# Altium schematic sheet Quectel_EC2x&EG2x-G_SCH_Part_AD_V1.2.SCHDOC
size A4
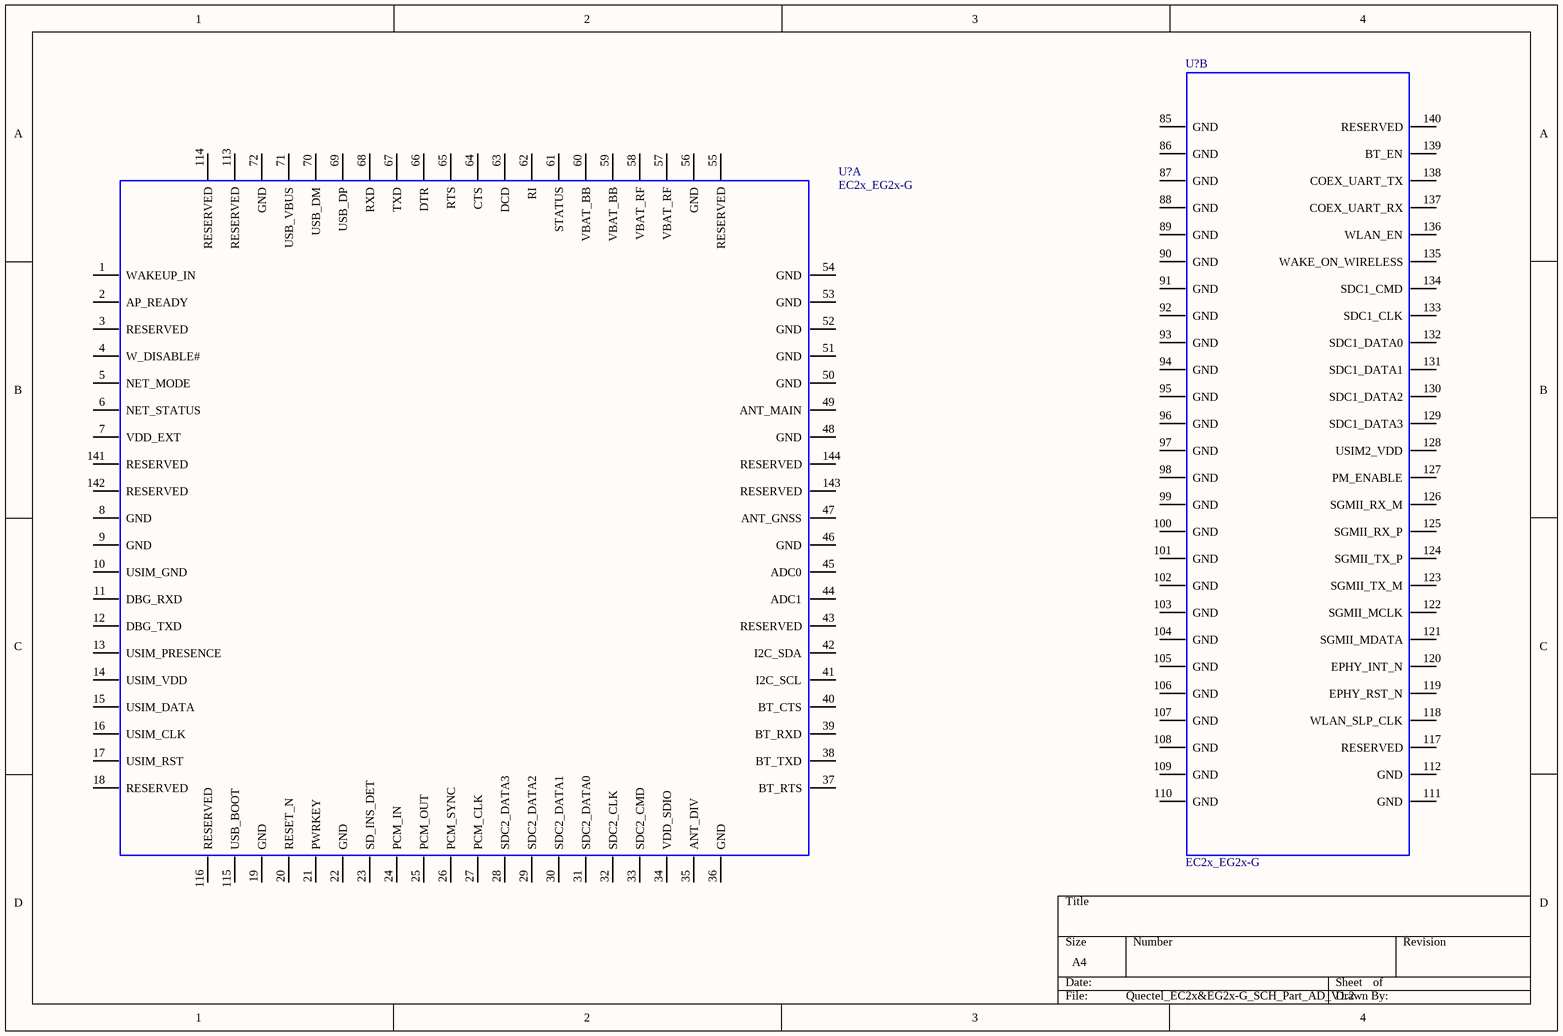
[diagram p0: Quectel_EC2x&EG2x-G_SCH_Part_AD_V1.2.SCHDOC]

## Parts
(Parts that share a designator on the sheet are numbered #1, #2 ... from top to bottom, then left to right.)
U?#1  EC2x_EG2x-G  (part B of 2)
U?#2  EC2x_EG2x-G  (part A of 2)

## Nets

Not connected (* = marked no-connect by the designer): U?#1 85(GND) 86(GND) 87(GND) 88(GND) 89(GND) 90(GND) 91(GND) 92(GND) 93(GND) 94(GND) 95(GND) 96(GND) 97(GND) 98(GND) 99(GND) 100(GND) 101(GND) 102(GND) 103(GND) 104(GND) 105(GND) 106(GND) 107(GND) 108(GND) 109(GND) 110(GND) 111(GND) 112(GND) 117(RESERVED) 118(WLAN_SLP_CLK) 119(EPHY_RST_N) 120(EPHY_INT_N) 121(SGMII_MDATA) 122(SGMII_MCLK) 123(SGMII_TX_M) 124(SGMII_TX_P) 125(SGMII_RX_P) 126(SGMII_RX_M) 127(PM_ENABLE) 128(USIM2_VDD) 129(SDC1_DATA3) 130(SDC1_DATA2) 131(SDC1_DATA1) 132(SDC1_DATA0) 133(SDC1_CLK) 134(SDC1_CMD) 135(WAKE_ON_WIRELESS) 136(WLAN_EN) 137(COEX_UART_RX) 138(COEX_UART_TX) 139(BT_EN) 140(RESERVED); U?#2 1(WAKEUP_IN) 2(AP_READY) 3(RESERVED) 4(W_DISABLE#) 5(NET_MODE) 6(NET_STATUS) 7(VDD_EXT) 8(GND) 9(GND) 10(USIM_GND) 11(DBG_RXD) 12(DBG_TXD) 13(USIM_PRESENCE) 14(USIM_VDD) 15(USIM_DATA) 16(USIM_CLK) 17(USIM_RST) 18(RESERVED) 19(GND) 20(RESET_N) 21(PWRKEY) 22(GND) 23(SD_INS_DET) 24(PCM_IN) 25(PCM_OUT) 26(PCM_SYNC) 27(PCM_CLK) 28(SDC2_DATA3) 29(SDC2_DATA2) 30(SDC2_DATA1) 31(SDC2_DATA0) 32(SDC2_CLK) 33(SDC2_CMD) 34(VDD_SDIO) 35(ANT_DIV) 36(GND) 37(BT_RTS) 38(BT_TXD) 39(BT_RXD) 40(BT_CTS) 41(I2C_SCL) 42(I2C_SDA) 43(RESERVED) 44(ADC1) 45(ADC0) 46(GND) 47(ANT_GNSS) 48(GND) 49(ANT_MAIN) 50(GND) 51(GND) 52(GND) 53(GND) 54(GND) 55(RESERVED) 56(GND) 57(VBAT_RF) 58(VBAT_RF) 59(VBAT_BB) 60(VBAT_BB) 61(STATUS) 62(RI) 63(DCD) 64(CTS) 65(RTS) 66(DTR) 67(TXD) 68(RXD) 69(USB_DP) 70(USB_DM) 71(USB_VBUS) 72(GND) 113(RESERVED) 114(RESERVED) 115(USB_BOOT) 116(RESERVED) 141(RESERVED) 142(RESERVED) 143(RESERVED) 144(RESERVED)

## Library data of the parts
U?#1 U?#2 = EG25-G_EC25_EC21_EG21G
